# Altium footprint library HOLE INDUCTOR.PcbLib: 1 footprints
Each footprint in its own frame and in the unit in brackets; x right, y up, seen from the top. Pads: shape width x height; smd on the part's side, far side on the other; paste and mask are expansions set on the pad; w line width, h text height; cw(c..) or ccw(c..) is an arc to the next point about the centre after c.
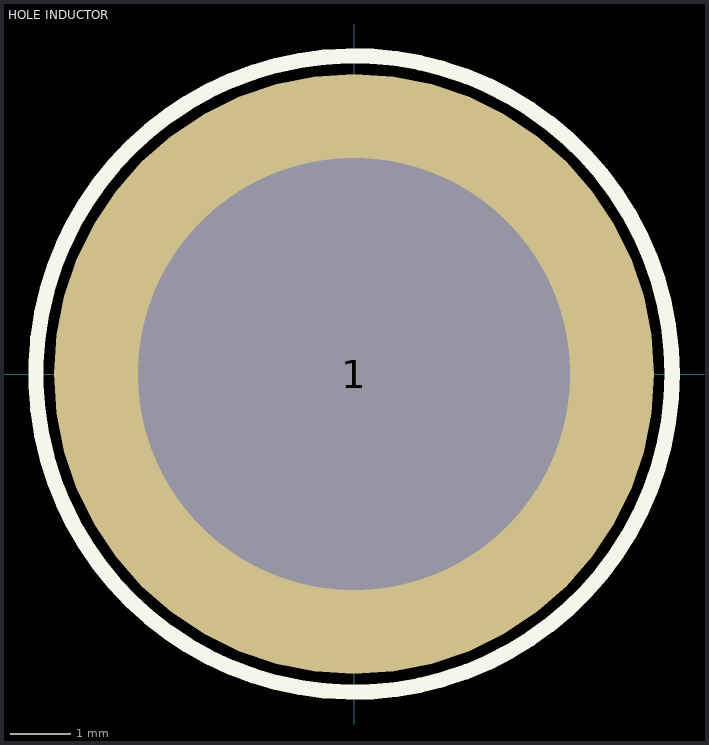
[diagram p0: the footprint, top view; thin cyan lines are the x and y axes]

## HOLE INDUCTOR [mm] "M3 X0.5 HOLE NO METAL"
height 2.4
pads (1):
  round 10 hole 7.2: 1(0,0)
Top Overlay:
  circle w0.254: c0,0 r5.3
M5 Assembly Top:
  text ".Designator" at -0.1,-0.1 h1.02
3D body: height 2.5, standoff 0, extent -5.45,-5.4 5.5,5.4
